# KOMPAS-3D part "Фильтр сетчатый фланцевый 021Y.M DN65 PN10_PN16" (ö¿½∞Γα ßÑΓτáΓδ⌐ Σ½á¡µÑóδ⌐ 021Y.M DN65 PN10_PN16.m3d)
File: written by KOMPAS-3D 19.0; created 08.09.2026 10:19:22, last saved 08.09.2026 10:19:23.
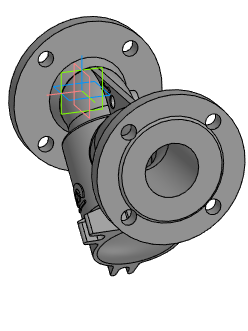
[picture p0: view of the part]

Document properties: Автор: Энергия; Полное имя файла: Z:\3.Личные\sachek\Dendor\_3D для проектировщиков\8.2 Фильтр сетчатый 021Y.M\021Y.M_STP\Фильтр сетчатый фланцевый 021Y.M DN65 PN10_PN16.m3d

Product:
- Part/product: Фильтр сетчатый фланцевый 021Y.M DN65 PN10_PN16
    Масса: 13.846

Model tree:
1. Операция без истории:1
